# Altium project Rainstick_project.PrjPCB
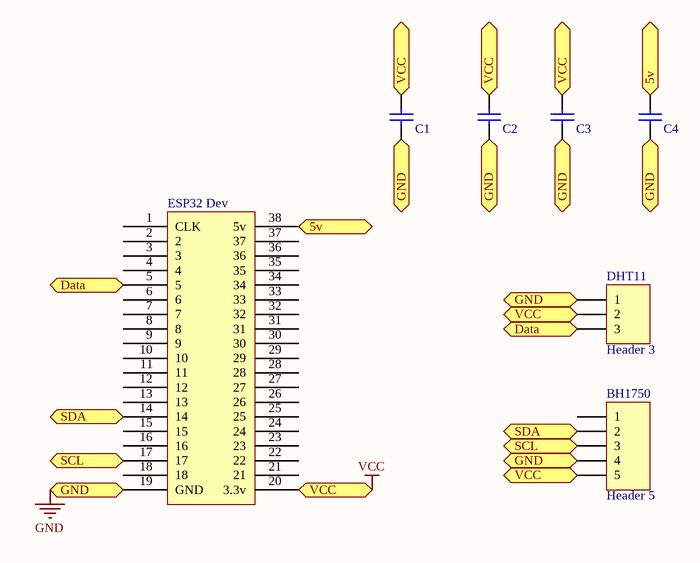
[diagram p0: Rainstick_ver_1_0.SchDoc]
1 sheet, 7 parts. Net scope: flat (ports and power ports of the same name join across sheets).
Board file: Rainstick_ver_1_0.PcbDoc

## Sheet Rainstick_ver_1_0.SchDoc
size A4

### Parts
BH1750  Header 5  [HDR1X5]
C1  Cap  [My_cap100n]  (value not drawn)
C2  Cap  [My_cap100n]  (value not drawn)
C3  Cap  [My_cap100n]  (value not drawn)
C4  Cap  [My_cap100n]  (value not drawn)
DHT11  Header 3  [HDR1X3]
ESP32_Dev  (no value)  [PCBComponent_1]

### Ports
5v, Data, GND, SCL, SDA, VCC

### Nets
GND: BH1750.4 C1.1 C2.1 C3.1 C4.1 DHT11.1 ESP32_Dev.19(GND) ; port GND
VCC: BH1750.5 C1.2 C2.2 C3.2 DHT11.2 ESP32_Dev.20(3.3v) ; port VCC
NetBH1750_2: BH1750.2 ESP32_Dev.14 ; port SDA
NetBH1750_3: BH1750.3 ESP32_Dev.17 ; port SCL
NetC4_2: C4.2 ESP32_Dev.38(5v) ; port 5v
NetDHT11_3: DHT11.3 ESP32_Dev.5 ; port Data

Not connected (* = marked no-connect by the designer): BH1750 1; ESP32_Dev 1(CLK) 2 3 4 6 7 8 9 10 11 12 13 15 16 18 21 22 23 24 25 26 27 28 29 30 31 32 33 34 35 36 37

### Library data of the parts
BH1750 = Header 5: Header, 5-Pin
C1-C4 = Cap ceramic: CAP-100Nf; Value: 100nF
DHT11 = Header 3: Header, 3-Pin
ESP32_Dev = Component_1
